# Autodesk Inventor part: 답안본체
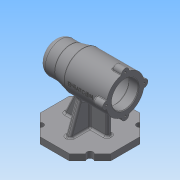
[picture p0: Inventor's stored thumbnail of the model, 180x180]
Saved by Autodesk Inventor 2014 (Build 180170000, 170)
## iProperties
Created: 2019-12
Part Number: 답안본체
Material: 일반
Document SubType Name: Modeling
Designer: net
Density: 1 g/cm^3
Appearance: 기본값
Author: net
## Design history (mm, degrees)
sketch "스케치1"
  geometry: L1 (56, 0)-(-56, 0); L2 (56, 0)-(56, 25); L3 (56, 25)-(31, 25); L4 (31, 25)-(11, 30); L5 (11, 30)-(-56, 30); L6 (-56, 30)-(-56, 21); L7 (-56, 21)-(-41, 21); L8 (-41, 21)-(-41, 24); L9 (-41, 24)-(13, 24); L10 (13, 24)-(13, 21); L11 (13, 21)-(25, 21); L12 (25, 21)-(25, 17.5); L13 (25, 17.5)-(43, 17.5); L14 (43, 17.5)-(43, 16); L15 (43, 16)-(47, 16); L16 (47, 16)-(47, 10.5); L17 (47, 10.5)-(50, 10.5); L18 (50, 10.5)-(50, 0); 4 further points
  constraints: 36 end point, 14 parallel, 3 midpoint, 2 perpendicular, 2 vertical alignment, 1 coincident, 1 horizontal, 1 point on line
  dimensions: "d0" = 112 distance of L1.start L1.end; "d1" = 3 distance of L16.end L17.end; "d2" = 4 distance of L14.end L15.end; "d3" = 18 distance of L12.end L13.end; "d4" = 12 distance of L10.end L11.end; "d5" = 54 distance of L8.end L9.end; "d6" = 15 distance of L6.end L7.end; "d7" = 25 distance of L2.end L3.end; "d8" = 45 distance from line of L4.end L2; "d9" = 21 diameter of L17 L1; "d10" = 32 diameter of L15 L1; "d11" = 50 diameter of L3 L1; "d12" = 60 diameter of L5 L1; "d13" = 42 diameter of L7 L1; "d14" = 42 diameter of L11 L1; "d15" = 48 diameter of L9 L1; "d16" = 35 diameter of L13 L1
revolve "회전1" sketch "스케치1" stored, may be unused: angle "d17" = 90 deg
fillet "모깎기1" dims "d18" = 10
fillet "모깎기2" dims "d19" = 0.3
fillet "모깎기3" dims "d20" = 3
sketch "스케치2"
  geometry: A1 r 30 centre (0, 0) between (-30, 0) and (-29.4, -5.97) reference; A2 r 6 centre (-30, 0) between (-29.4, 5.97) and (-29.4, -5.97)
  constraints: 5 point on circle, 1 centre point, 1 horizontal alignment
  dimensions: "d21" = 12 diameter of A2
extrude "돌출1" join sketch "스케치2" distance "d22" = 16; taper "d23" = 0 deg
sketch "스케치3"
  geometry: A1 r 6 centre (0, 0) between (0.6, 5.97) and (0.6, -5.97) reference; 1 further point
  constraints: 1 coincident
hole "구멍1" sketch "스케치3" at (0, 0) diameter "d27" = 3.242; stored, may be unused: countersink angle "d31" = 90 deg, drill point angle "d33" = 118 deg; dims "d28" = 8, "d29" = 4, "d30" = 2, "d32" = 11
fillet "모깎기4" dims "d37" = 3
fillet "모깎기5" dims "d38" = 1
node "작업 평면1"
sketch "스케치4" dims "d40" = 112
  geometry: L1 (23.196, 56)-(56, 23.196); L2 (56, 23.196)-(56, -23.196); L3 (56, -23.196)-(23.196, -56); L4 (23.196, -56)-(-23.196, -56); L5 (-23.196, -56)-(-56, -23.196); L6 (-56, -23.196)-(-56, 23.196); L7 (-56, 23.196)-(-23.196, 56); L8 (-23.196, 56)-(23.196, 56); 4 further points
  constraints: 16 end point, 2 coincident, 2 vertical alignment, 1 midpoint, 19 other
extrude "돌출2" join sketch "스케치4" distance "d41" = 10; taper "d42" = 0 deg
sketch "스케치5"
  geometry: L1 (56, 23.196)-(23.196, 56) reference; L2 (-23.196, 56)-(-56, 23.196) reference; L3 (-56, -23.196)-(-23.196, -56) reference; L4 (23.196, -56)-(56, -23.196) reference; C1 r 5 at (39.598, 39.598); C2 r 5 at (39.598, -39.598); C3 r 5 at (-39.598, -39.598); C4 r 5 at (-39.598, 39.598); 4 further points
  constraints: 7 midpoint, 4 centre point, 2 horizontal alignment, 2 vertical alignment
  dimensions: "d44" = 10 diameter of C1; "d45" = 10 diameter of C2; "d46" = 10 diameter of C3; "d47" = 10 diameter of C4
extrude "돌출3" cut sketch "스케치5" distance "d48" = 10; taper "d49" = 0 deg
sketch "스케치6"
  geometry: L1 (56, -23.196)-(56, 23.196) reference; L2 (0, 4)-(31, 4); L3 (31, 4)-(31, -4); L4 (31, -4)-(0, -4); L5 (0, -4)-(0, 4); 2 further points
  constraints: 8 end point, 2 parallel, 1 coincident, 1 horizontal, 1 midpoint, 1 perpendicular
  dimensions: "d50" = 8 distance of L2.end L3.end; "d51" = 25 distance between parallel lines of L1 L3
extrude "돌출4" join sketch "스케치6" stored distance "d52" = 10; taper "d53" = 0 deg
sketch "스케치7"
  geometry: L1 (56, 15)-(56, -15) reference; L2 (46, -25)-(31, -25) reference; L3 (31, -25)-(11, -30) reference; L4 (11, -30)-(0, -30) reference; L5 (0, -30)-(0, -70) reference; L6 (0, -70)-(56, -70) reference; L7 (56, -70)-(56, -80) reference; L8 (56, -80)-(-56, -80) reference; L9 (-56, -80)-(-56, -70) reference; L10 (-56, -70)-(-31, -70) reference; L11 (-31, -70)-(-31, -30) reference; L12 (-31, -30)-(-39, -30) reference; L13 (-40, -31)-(-40, -33) reference; L14 (-43, -36)-(-56, -36) reference; L15 (-56, -36)-(-56, -31.621) reference; L16 (-56, -31.621)-(-45, -31.621) reference; L17 (-45, -31.621)-(-44.026, -30) reference; L18 (-44.026, -30)-(-45, -28.379) reference; L19 (-45, -28.379)-(-56, -28.379) reference; L20 (-56, -28.379)-(-56, -21) reference; L21 (-56, -21)-(-41, -21) reference; L22 (-38, -24)-(10, -24) reference; L23 (13, -21)-(24.7, -21) reference; L24 (25, -20.7)-(25, -17.5) reference; L25 (25, -17.5)-(42.7, -17.5) reference; L26 (43, -17.2)-(43, -16) reference; L27 (43, -16)-(46.7, -16) reference; L28 (47, -15.7)-(47, -10.5) reference; L29 (50, -7.5)-(50, 7.5) reference; L30 (47, 10.5)-(47, 15.7) reference; L31 (46.7, 16)-(43, 16) reference; L32 (43, 16)-(43, 17.2) reference; L33 (42.7, 17.5)-(25, 17.5) reference; L34 (25, 17.5)-(25, 20.7) reference; L35 (24.7, 21)-(13, 21) reference; L36 (10, 24)-(-38, 24) reference; L37 (-41, 21)-(-56, 21) reference; L38 (-56, 21)-(-56, 28.379) reference; L39 (-56, 28.379)-(-45, 28.379) reference; L40 (-45, 28.379)-(-44.026, 30) reference; L41 (-44.026, 30)-(-45, 31.621) reference; L42 (-45, 31.621)-(-56, 31.621) reference; L43 (-56, 31.621)-(-56, 36) reference; L44 (-56, 36)-(-43, 36) reference; L45 (-40, 33)-(-40, 31) reference; L46 (-39, 30)-(11, 30) reference; L47 (11, 30)-(31, 25) reference; L48 (31, 25)-(46, 25) reference; L49 (18.476, -28.131)-(38, -70); A1 r 10 centre (46, 15) between (56, 15) and (46, 25) reference; A2 r 10 centre (46, -15) between (46, -25) and (56, -15) reference; A3 r 1 centre (-39, -31) between (-39, -30) and (-40, -31) reference; A4 r 3 centre (-43, -33) between (-43, -36) and (-40, -33) reference; A5 r 3 centre (-38, -21) between (-41, -21) and (-38, -24) reference; A6 r 3 centre (10, -21) between (10, -24) and (13, -21) reference; A7 r 0.3 centre (24.7, -20.7) between (24.7, -21) and (25, -20.7) reference; A8 r 0.3 centre (42.7, -17.2) between (42.7, -17.5) and (43, -17.2) reference; A9 r 0.3 centre (46.7, -15.7) between (46.7, -16) and (47, -15.7) reference; A10 r 3 centre (47, -7.5) between (47, -10.5) and (50, -7.5) reference; A11 r 3 centre (47, 7.5) between (50, 7.5) and (47, 10.5) reference; A12 r 0.3 centre (46.7, 15.7) between (47, 15.7) and (46.7, 16) reference; A13 r 0.3 centre (42.7, 17.2) between (43, 17.2) and (42.7, 17.5) reference; A14 r 0.3 centre (24.7, 20.7) between (25, 20.7) and (24.7, 21) reference; A15 r 3 centre (10, 21) between (13, 21) and (10, 24) reference; A16 r 3 centre (-38, 21) between (-38, 24) and (-41, 21) reference; A17 r 3 centre (-43, 33) between (-40, 33) and (-43, 36) reference; A18 r 1 centre (-39, 31) between (-40, 31) and (-39, 30) reference; 1 further point
  constraints: 2 end point, 2 point on line
  dimensions: "d54" = 115 deg angle of L6 L49; "d55" = 18 distance from line of L7 L49.end
feature "리브1" sketch "스케치7" dims "d56" = 1, "d57" = 8, "d58" = 0, "d59" = 0, "d60" = 1, "d61" = 1
sketch "스케치8"
  geometry: L1 (-56, -70)-(-4, -70) reference; L2 (-4, -70)-(-4, -29.732) reference; L3 (4, -29.732)-(4, -70) reference; L4 (4, -70)-(56, -70) reference; L5 (56, -70)-(56, -80) reference; L6 (56, -80)-(-56, -80) reference; L7 (-56, -80)-(-56, -70) reference; L8 (-18.979, -23.234)-(-36, -70); C1 r 24 at (0, 0) reference; A1 r 30 centre (0, 0) between (4, -29.732) and (-4, -29.732) reference; 1 further point
  constraints: 2 end point, 1 point on circle, 1 point on line
  dimensions: "d62" = 110 deg angle of L1 L8; "d63" = 20 distance from line of L7 L8.end
feature "리브2" sketch "스케치8" dims "d64" = 1, "d65" = 8, "d66" = 0, "d67" = 0, "d68" = 1, "d69" = 1
fillet "모깎기6" dims "d70" = 3
chamfer "모따기1" distance "d74" = 1; stored, may be unused: second distance "d75" = 2, angle "d76" = 45 deg
sketch "스케치10"
  geometry: L1 (56, -80)-(-56, -80) reference; L2 (-56, -80)-(-56, -70) reference; L3 (-56, -70)-(-36, -70) reference; L4 (-36, -70)-(-18.979, -23.234) reference; L5 (4, -29.732)-(4, -70) reference; L6 (4, -70)-(56, -70) reference; L7 (56, -70)-(56, -80) reference; L8 (18.979, -23.234)-(36, -70); C1 r 24 at (0, 0) reference; A1 r 30 centre (0, 0) between (4, -29.732) and (-18.979, -23.234) reference; 1 further point
  constraints: 2 end point, 1 point on line
  dimensions: "d80" = 20 distance from line of L7 L8.end; "d81" = 110 deg angle of L6 L8
feature "리브3" sketch "스케치10" dims "d82" = 1, "d83" = 8, "d84" = 0, "d85" = 0, "d86" = 1, "d87" = 1
fillet "모깎기10" dims "d88" = 3
fillet "모깎기11" dims "d89" = 3
fillet "모깎기12" dims "d90" = 3
node "작업 평면3"
sketch "스케치11"
  geometry: L1 (33.5, 29.226)-(33.5, 6.771) reference; 2 further points
  constraints: 1 horizontal alignment, 1 other
  dimensions: "d91" = 41 distance from line of L1 point (-7.5, 0)
feature "엠보싱2" sketch "스케치11" dims "d92" = 0.5, "d93" = 0
node "솔리드1"
pattern_circular "원형 패턴1" dims angle "d25" = 360 deg
pattern_circular "원형 패턴2" dims angle "d35" = 360 deg
node "절단 모서리 투영1"
node "절단 모서리 투영2"
node "절단 모서리 투영3"
